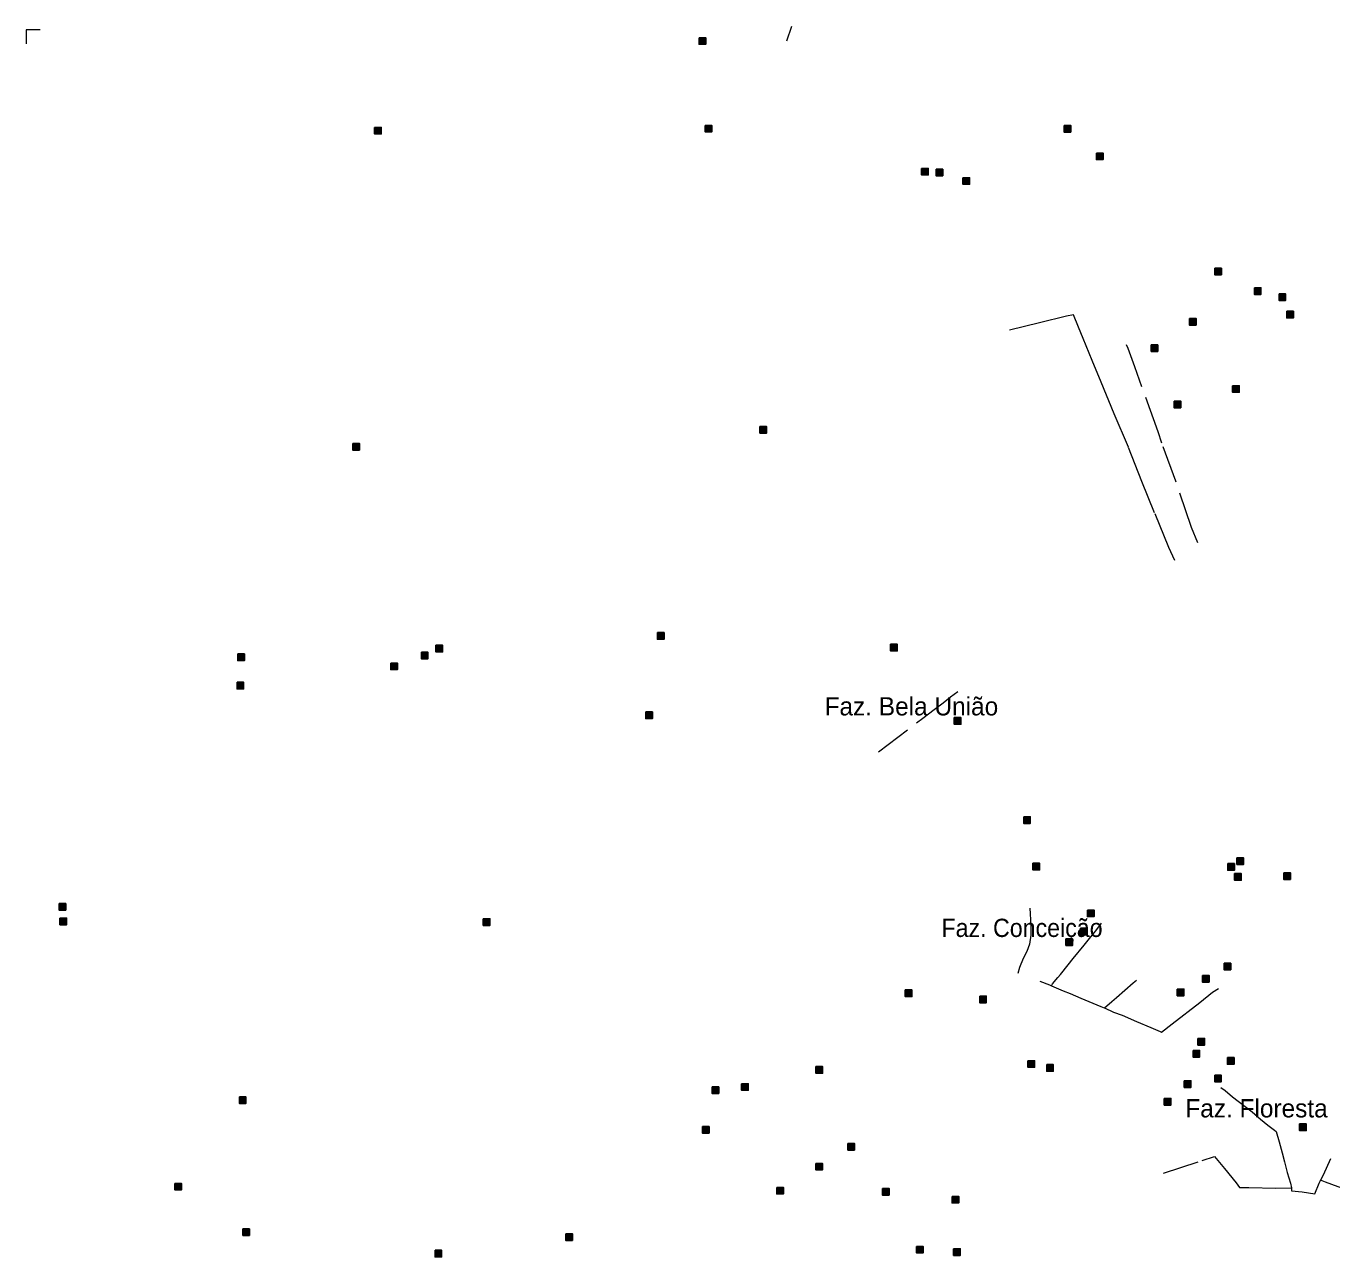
# Model space of a CAD drawing. Extents: x 393.5 to 446.9, y 8064.8 to 8120.4.
# Drawn here: x 393.54 to 404.99, y 8109.39 to 8120.19 of the extents above; entities that cross this region are included whole.
import ezdxf

# ---------------------------------------------------------------- set-up
doc = ezdxf.new("R2010")
doc.units = 0
doc.header["$LTSCALE"] = 0.064
doc.linetypes.add('DOT_DASHED', pattern=[7.7, 5, -1.2, 0.3, -1.2])
for name, color, linetype, lineweight in [('2', 7, 'Continuous', 25), ('22', 7, 'DOT_DASHED', 13), ('63', 7, 'Continuous', 13)]:
    doc.layers.add(name, color=color, linetype=linetype, lineweight=lineweight)
doc.layers.add('61', color=7, linetype='Continuous')

msp = doc.modelspace()

# ---------------------------------------------------------------- hatches: boundary and pattern name
at = {"layer": '2'}
for points in [[(399.4403, 8120.0847), (399.4983, 8120.0847), (399.4983, 8120.0267), (399.4403, 8120.0267)], [(399.4938, 8119.3158), (399.5518, 8119.3158), (399.5518, 8119.2578), (399.4938, 8119.2578)], [(402.6411, 8119.3152), (402.6991, 8119.3152), (402.6991, 8119.2572), (402.6411, 8119.2572)], [(396.5954, 8119.2985), (396.6534, 8119.2985), (396.6534, 8119.2405), (396.5954, 8119.2405)], [(402.9245, 8119.0735), (402.9825, 8119.0735), (402.9825, 8119.0155), (402.9245, 8119.0155)], [(401.3912, 8118.939), (401.4492, 8118.939), (401.4492, 8118.881), (401.3912, 8118.881)], [(401.5188, 8118.9317), (401.5768, 8118.9317), (401.5768, 8118.8737), (401.5188, 8118.8737)], [(401.7537, 8118.8571), (401.8117, 8118.8571), (401.8117, 8118.7991), (401.7537, 8118.7991)], [(403.962, 8118.0636), (404.02, 8118.0636), (404.02, 8118.0056), (403.962, 8118.0056)], [(404.3084, 8117.8916), (404.3664, 8117.8916), (404.3664, 8117.8336), (404.3084, 8117.8336)], [(404.525, 8117.8386), (404.583, 8117.8386), (404.583, 8117.7806), (404.525, 8117.7806)], [(403.7391, 8117.6229), (403.7971, 8117.6229), (403.7971, 8117.5649), (403.7391, 8117.5649)], [(404.5926, 8117.6855), (404.6506, 8117.6855), (404.6506, 8117.6275), (404.5926, 8117.6275)], [(403.4041, 8117.3912), (403.4621, 8117.3912), (403.4621, 8117.3332), (403.4041, 8117.3332)], [(404.1183, 8117.0334), (404.1763, 8117.0334), (404.1763, 8116.9754), (404.1183, 8116.9754)], [(403.6054, 8116.8983), (403.6634, 8116.8983), (403.6634, 8116.8403), (403.6054, 8116.8403)], [(399.974, 8116.6752), (400.032, 8116.6752), (400.032, 8116.6172), (399.974, 8116.6172)], [(396.4044, 8116.5271), (396.4624, 8116.5271), (396.4624, 8116.4691), (396.4044, 8116.4691)], [(399.075, 8114.868), (399.133, 8114.868), (399.133, 8114.81), (399.075, 8114.81)], [(397.133, 8114.7574), (397.191, 8114.7574), (397.191, 8114.6994), (397.133, 8114.6994)], [(401.1191, 8114.7664), (401.1771, 8114.7664), (401.1771, 8114.7084), (401.1191, 8114.7084)], [(395.3962, 8114.6811), (395.4542, 8114.6811), (395.4542, 8114.6231), (395.3962, 8114.6231)], [(397.0057, 8114.6965), (397.0637, 8114.6965), (397.0637, 8114.6385), (397.0057, 8114.6385)], [(396.7378, 8114.6018), (396.7958, 8114.6018), (396.7958, 8114.5438), (396.7378, 8114.5438)], [(395.3893, 8114.4324), (395.4473, 8114.4324), (395.4473, 8114.3744), (395.3893, 8114.3744)], [(398.9733, 8114.1723), (399.0313, 8114.1723), (399.0313, 8114.1143), (398.9733, 8114.1143)], [(401.6779, 8114.1229), (401.7359, 8114.1229), (401.7359, 8114.0649), (401.6779, 8114.0649)], [(402.2864, 8113.2538), (402.3444, 8113.2538), (402.3444, 8113.1958), (402.2864, 8113.1958)], [(402.3674, 8112.8458), (402.4254, 8112.8458), (402.4254, 8112.7878), (402.3674, 8112.7878)], [(404.0754, 8112.8425), (404.1334, 8112.8425), (404.1334, 8112.7845), (404.0754, 8112.7845)], [(404.1564, 8112.8933), (404.2144, 8112.8933), (404.2144, 8112.8353), (404.1564, 8112.8353)], [(404.1359, 8112.7551), (404.1939, 8112.7551), (404.1939, 8112.6971), (404.1359, 8112.6971)], [(404.5662, 8112.7621), (404.6242, 8112.7621), (404.6242, 8112.7041), (404.5662, 8112.7041)], [(393.8298, 8112.493), (393.8878, 8112.493), (393.8878, 8112.435), (393.8298, 8112.435)], [(393.8365, 8112.365), (393.8945, 8112.365), (393.8945, 8112.307), (393.8365, 8112.307)], [(397.548, 8112.3591), (397.606, 8112.3591), (397.606, 8112.3011), (397.548, 8112.3011)], [(402.8452, 8112.4361), (402.9032, 8112.4361), (402.9032, 8112.3781), (402.8452, 8112.3781)], [(402.7843, 8112.2773), (402.8423, 8112.2773), (402.8423, 8112.2193), (402.7843, 8112.2193)], [(402.6566, 8112.1831), (402.7146, 8112.1831), (402.7146, 8112.1251), (402.6566, 8112.1251)], [(404.0439, 8111.9698), (404.1019, 8111.9698), (404.1019, 8111.9118), (404.0439, 8111.9118)], [(403.8534, 8111.8626), (403.9114, 8111.8626), (403.9114, 8111.8046), (403.8534, 8111.8046)], [(401.2482, 8111.7356), (401.3062, 8111.7356), (401.3062, 8111.6776), (401.2482, 8111.6776)], [(401.9004, 8111.6812), (401.9584, 8111.6812), (401.9584, 8111.6232), (401.9004, 8111.6232)], [(403.6333, 8111.7423), (403.6913, 8111.7423), (403.6913, 8111.6843), (403.6333, 8111.6843)], [(403.8138, 8111.3103), (403.8718, 8111.3103), (403.8718, 8111.2523), (403.8138, 8111.2523)], [(403.7707, 8111.205), (403.8287, 8111.205), (403.8287, 8111.147), (403.7707, 8111.147)], [(402.3236, 8111.1151), (402.3816, 8111.1151), (402.3816, 8111.0571), (402.3236, 8111.0571)], [(402.4878, 8111.0805), (402.5458, 8111.0805), (402.5458, 8111.0225), (402.4878, 8111.0225)], [(404.0729, 8111.1421), (404.1309, 8111.1421), (404.1309, 8111.0841), (404.0729, 8111.0841)], [(400.4649, 8111.0626), (400.5229, 8111.0626), (400.5229, 8111.0046), (400.4649, 8111.0046)], [(403.9608, 8110.9877), (404.0188, 8110.9877), (404.0188, 8110.9297), (403.9608, 8110.9297)], [(399.5543, 8110.8855), (399.6123, 8110.8855), (399.6123, 8110.8275), (399.5543, 8110.8275)], [(399.813, 8110.9134), (399.871, 8110.9134), (399.871, 8110.8554), (399.813, 8110.8554)], [(403.6938, 8110.9385), (403.7518, 8110.9385), (403.7518, 8110.8805), (403.6938, 8110.8805)], [(395.4101, 8110.7976), (395.4681, 8110.7976), (395.4681, 8110.7396), (395.4101, 8110.7396)], [(403.5184, 8110.784), (403.5764, 8110.784), (403.5764, 8110.726), (403.5184, 8110.726)], [(399.4703, 8110.5378), (399.5283, 8110.5378), (399.5283, 8110.4798), (399.4703, 8110.4798)], [(404.7057, 8110.5603), (404.7637, 8110.5603), (404.7637, 8110.5023), (404.7057, 8110.5023)], [(400.7448, 8110.3893), (400.8028, 8110.3893), (400.8028, 8110.3313), (400.7448, 8110.3313)], [(400.464, 8110.2147), (400.522, 8110.2147), (400.522, 8110.1567), (400.464, 8110.1567)], [(394.8446, 8110.0392), (394.9026, 8110.0392), (394.9026, 8109.9812), (394.8446, 8109.9812)], [(400.1214, 8110.0042), (400.1794, 8110.0042), (400.1794, 8109.9462), (400.1214, 8109.9462)], [(401.0482, 8109.9946), (401.1062, 8109.9946), (401.1062, 8109.9366), (401.0482, 8109.9366)], [(401.6586, 8109.9253), (401.7166, 8109.9253), (401.7166, 8109.8673), (401.6586, 8109.8673)], [(395.4406, 8109.6405), (395.4986, 8109.6405), (395.4986, 8109.5825), (395.4406, 8109.5825)], [(398.2716, 8109.5972), (398.3296, 8109.5972), (398.3296, 8109.5392), (398.2716, 8109.5392)], [(401.3467, 8109.4868), (401.4047, 8109.4868), (401.4047, 8109.4288), (401.3467, 8109.4288)], [(401.672, 8109.4663), (401.73, 8109.4663), (401.73, 8109.4083), (401.672, 8109.4083)], [(397.1255, 8109.4527), (397.1835, 8109.4527), (397.1835, 8109.3947), (397.1255, 8109.3947)]]:
    msp.add_hatch(color=256, dxfattribs=at).paths.add_polyline_path(points)

# ---------------------------------------------------------------- linework, layer by layer
for points in [[(399.4403, 8120.0847), (399.4983, 8120.0847), (399.4983, 8120.0267), (399.4403, 8120.0267)], [(399.4938, 8119.3158), (399.5518, 8119.3158), (399.5518, 8119.2578), (399.4938, 8119.2578)], [(402.6411, 8119.3152), (402.6991, 8119.3152), (402.6991, 8119.2572), (402.6411, 8119.2572)], [(396.5954, 8119.2985), (396.6534, 8119.2985), (396.6534, 8119.2405), (396.5954, 8119.2405)], [(402.9245, 8119.0735), (402.9825, 8119.0735), (402.9825, 8119.0155), (402.9245, 8119.0155)], [(401.3912, 8118.939), (401.4492, 8118.939), (401.4492, 8118.881), (401.3912, 8118.881)], [(401.5188, 8118.9317), (401.5768, 8118.9317), (401.5768, 8118.8737), (401.5188, 8118.8737)], [(401.7537, 8118.8571), (401.8117, 8118.8571), (401.8117, 8118.7991), (401.7537, 8118.7991)], [(403.962, 8118.0636), (404.02, 8118.0636), (404.02, 8118.0056), (403.962, 8118.0056)], [(404.3084, 8117.8916), (404.3664, 8117.8916), (404.3664, 8117.8336), (404.3084, 8117.8336)], [(404.525, 8117.8386), (404.583, 8117.8386), (404.583, 8117.7806), (404.525, 8117.7806)], [(403.7391, 8117.6229), (403.7971, 8117.6229), (403.7971, 8117.5649), (403.7391, 8117.5649)], [(404.5926, 8117.6855), (404.6506, 8117.6855), (404.6506, 8117.6275), (404.5926, 8117.6275)], [(403.4041, 8117.3912), (403.4621, 8117.3912), (403.4621, 8117.3332), (403.4041, 8117.3332)], [(404.1183, 8117.0334), (404.1763, 8117.0334), (404.1763, 8116.9754), (404.1183, 8116.9754)], [(403.6054, 8116.8983), (403.6634, 8116.8983), (403.6634, 8116.8403), (403.6054, 8116.8403)], [(399.974, 8116.6752), (400.032, 8116.6752), (400.032, 8116.6172), (399.974, 8116.6172)], [(396.4044, 8116.5271), (396.4624, 8116.5271), (396.4624, 8116.4691), (396.4044, 8116.4691)], [(399.075, 8114.868), (399.133, 8114.868), (399.133, 8114.81), (399.075, 8114.81)], [(397.133, 8114.7574), (397.191, 8114.7574), (397.191, 8114.6994), (397.133, 8114.6994)], [(401.1191, 8114.7664), (401.1771, 8114.7664), (401.1771, 8114.7084), (401.1191, 8114.7084)], [(395.3962, 8114.6811), (395.4542, 8114.6811), (395.4542, 8114.6231), (395.3962, 8114.6231)], [(397.0057, 8114.6965), (397.0637, 8114.6965), (397.0637, 8114.6385), (397.0057, 8114.6385)], [(396.7378, 8114.6018), (396.7958, 8114.6018), (396.7958, 8114.5438), (396.7378, 8114.5438)], [(395.3893, 8114.4324), (395.4473, 8114.4324), (395.4473, 8114.3744), (395.3893, 8114.3744)], [(398.9733, 8114.1723), (399.0313, 8114.1723), (399.0313, 8114.1143), (398.9733, 8114.1143)], [(401.6779, 8114.1229), (401.7359, 8114.1229), (401.7359, 8114.0649), (401.6779, 8114.0649)], [(402.2864, 8113.2538), (402.3444, 8113.2538), (402.3444, 8113.1958), (402.2864, 8113.1958)], [(402.3674, 8112.8458), (402.4254, 8112.8458), (402.4254, 8112.7878), (402.3674, 8112.7878)], [(404.0754, 8112.8425), (404.1334, 8112.8425), (404.1334, 8112.7845), (404.0754, 8112.7845)], [(404.1564, 8112.8933), (404.2144, 8112.8933), (404.2144, 8112.8353), (404.1564, 8112.8353)], [(404.1359, 8112.7551), (404.1939, 8112.7551), (404.1939, 8112.6971), (404.1359, 8112.6971)], [(404.5662, 8112.7621), (404.6242, 8112.7621), (404.6242, 8112.7041), (404.5662, 8112.7041)], [(393.8298, 8112.493), (393.8878, 8112.493), (393.8878, 8112.435), (393.8298, 8112.435)], [(393.8365, 8112.365), (393.8945, 8112.365), (393.8945, 8112.307), (393.8365, 8112.307)], [(397.548, 8112.3591), (397.606, 8112.3591), (397.606, 8112.3011), (397.548, 8112.3011)], [(402.8452, 8112.4361), (402.9032, 8112.4361), (402.9032, 8112.3781), (402.8452, 8112.3781)], [(402.7843, 8112.2773), (402.8423, 8112.2773), (402.8423, 8112.2193), (402.7843, 8112.2193)], [(402.6566, 8112.1831), (402.7146, 8112.1831), (402.7146, 8112.1251), (402.6566, 8112.1251)], [(404.0439, 8111.9698), (404.1019, 8111.9698), (404.1019, 8111.9118), (404.0439, 8111.9118)], [(403.8534, 8111.8626), (403.9114, 8111.8626), (403.9114, 8111.8046), (403.8534, 8111.8046)], [(401.2482, 8111.7356), (401.3062, 8111.7356), (401.3062, 8111.6776), (401.2482, 8111.6776)], [(401.9004, 8111.6812), (401.9584, 8111.6812), (401.9584, 8111.6232), (401.9004, 8111.6232)], [(403.6333, 8111.7423), (403.6913, 8111.7423), (403.6913, 8111.6843), (403.6333, 8111.6843)], [(403.8138, 8111.3103), (403.8718, 8111.3103), (403.8718, 8111.2523), (403.8138, 8111.2523)], [(403.7707, 8111.205), (403.8287, 8111.205), (403.8287, 8111.147), (403.7707, 8111.147)], [(402.3236, 8111.1151), (402.3816, 8111.1151), (402.3816, 8111.0571), (402.3236, 8111.0571)], [(402.4878, 8111.0805), (402.5458, 8111.0805), (402.5458, 8111.0225), (402.4878, 8111.0225)], [(404.0729, 8111.1421), (404.1309, 8111.1421), (404.1309, 8111.0841), (404.0729, 8111.0841)], [(400.4649, 8111.0626), (400.5229, 8111.0626), (400.5229, 8111.0046), (400.4649, 8111.0046)], [(403.9608, 8110.9877), (404.0188, 8110.9877), (404.0188, 8110.9297), (403.9608, 8110.9297)], [(399.5543, 8110.8855), (399.6123, 8110.8855), (399.6123, 8110.8275), (399.5543, 8110.8275)], [(399.813, 8110.9134), (399.871, 8110.9134), (399.871, 8110.8554), (399.813, 8110.8554)], [(403.6938, 8110.9385), (403.7518, 8110.9385), (403.7518, 8110.8805), (403.6938, 8110.8805)], [(395.4101, 8110.7976), (395.4681, 8110.7976), (395.4681, 8110.7396), (395.4101, 8110.7396)], [(403.5184, 8110.784), (403.5764, 8110.784), (403.5764, 8110.726), (403.5184, 8110.726)], [(399.4703, 8110.5378), (399.5283, 8110.5378), (399.5283, 8110.4798), (399.4703, 8110.4798)], [(404.7057, 8110.5603), (404.7637, 8110.5603), (404.7637, 8110.5023), (404.7057, 8110.5023)], [(400.7448, 8110.3893), (400.8028, 8110.3893), (400.8028, 8110.3313), (400.7448, 8110.3313)], [(400.464, 8110.2147), (400.522, 8110.2147), (400.522, 8110.1567), (400.464, 8110.1567)], [(394.8446, 8110.0392), (394.9026, 8110.0392), (394.9026, 8109.9812), (394.8446, 8109.9812)], [(400.1214, 8110.0042), (400.1794, 8110.0042), (400.1794, 8109.9462), (400.1214, 8109.9462)], [(401.0482, 8109.9946), (401.1062, 8109.9946), (401.1062, 8109.9366), (401.0482, 8109.9366)], [(401.6586, 8109.9253), (401.7166, 8109.9253), (401.7166, 8109.8673), (401.6586, 8109.8673)], [(395.4406, 8109.6405), (395.4986, 8109.6405), (395.4986, 8109.5825), (395.4406, 8109.5825)], [(398.2716, 8109.5972), (398.3296, 8109.5972), (398.3296, 8109.5392), (398.2716, 8109.5392)], [(401.3467, 8109.4868), (401.4047, 8109.4868), (401.4047, 8109.4288), (401.3467, 8109.4288)], [(401.672, 8109.4663), (401.73, 8109.4663), (401.73, 8109.4083), (401.672, 8109.4083)], [(397.1255, 8109.4527), (397.1835, 8109.4527), (397.1835, 8109.3947), (397.1255, 8109.3947)]]:
    msp.add_lwpolyline(points, close=True, dxfattribs=at)
at = {"layer": '22'}
msp.add_line((400.2104, 8120.058), (400.255, 8120.1861), dxfattribs=at)
for points in [[(402.7664, 8117.546), (402.7226, 8117.6555), (402.6622, 8117.6416), (402.4253, 8117.5859), (402.1605, 8117.5209)], [(403.6108, 8115.4997), (403.5589, 8115.6135), (403.4334, 8115.9198), (403.3219, 8116.1936), (403.2046, 8116.493), (403.0781, 8116.7854), (402.9667, 8117.0648), (402.8877, 8117.2528), (402.8088, 8117.4478), (402.7664, 8117.546)], [(403.8123, 8115.6552), (403.7563, 8115.7885), (403.6193, 8116.1969), (403.4973, 8116.5288), (403.4648, 8116.6286), (403.3233, 8117.0232), (403.2616, 8117.2001), (403.2024, 8117.3591), (403.1881, 8117.3917)], [(401.0125, 8113.8228), (401.4008, 8114.1177), (401.5018, 8114.1934), (401.5791, 8114.2533), (401.6438, 8114.3038), (401.6754, 8114.3274), (401.7085, 8114.3511)], [(402.3406, 8112.453), (402.3491, 8112.3009), (402.3491, 8112.2147), (402.3386, 8112.137), (402.3133, 8112.0717), (402.2817, 8112.0108), (402.2501, 8111.9309), (402.2351, 8111.8786)], [(402.6194, 8111.8859), (402.7214, 8112.0095), (402.8174, 8112.1285), (402.8753, 8112.1996), (402.9183, 8112.2541), (402.9679, 8112.3202)], [(402.5313, 8111.7721), (402.54, 8111.7886), (402.5871, 8111.8431), (402.6078, 8111.8704), (402.6194, 8111.8859)], [(402.4291, 8111.8117), (402.5118, 8111.7786), (402.5313, 8111.7721)], [(402.5313, 8111.7721), (402.5722, 8111.753), (402.6318, 8111.7266), (402.693, 8111.7034), (402.7873, 8111.6621), (402.9631, 8111.5887), (402.9927, 8111.5781), (402.9954, 8111.5771)], [(402.9954, 8111.5771), (403.0588, 8111.6344), (403.0992, 8111.6683), (403.1745, 8111.7326), (403.2471, 8111.7987), (403.2756, 8111.8216)], [(402.9954, 8111.5771), (403.0728, 8111.5408), (403.1489, 8111.5143), (403.2758, 8111.459), (403.4018, 8111.4061), (403.4819, 8111.37), (403.4946, 8111.3637), (403.5874, 8111.4372), (403.8309, 8111.626), (403.9413, 8111.7156), (403.9943, 8111.7479)], [(404.0142, 8110.879), (404.053, 8110.853), (404.1172, 8110.7973), (404.2894, 8110.6658), (404.3628, 8110.6033), (404.427, 8110.551), (404.4843, 8110.5071), (404.5012, 8110.4936), (404.5274, 8110.4043), (404.551, 8110.3081), (404.5737, 8110.2271), (404.5974, 8110.136), (404.6261, 8110.0415), (404.6347, 8109.9996)], [(403.5117, 8110.1301), (403.8522, 8110.2408), (403.9586, 8110.2762), (404.0463, 8110.17), (404.1493, 8110.0435), (404.1797, 8110.003), (404.2607, 8110.003), (404.4979, 8109.9962), (404.6294, 8109.9995), (404.6328, 8109.9996), (404.633, 8109.9996), (404.6347, 8109.9996)], [(404.9757, 8110.2543), (404.9115, 8110.1109), (404.8896, 8110.067)], [(404.6347, 8109.9996), (404.633, 8109.9743), (404.7275, 8109.9641), (404.8389, 8109.949), (404.8778, 8110.04), (404.8881, 8110.0636), (404.8896, 8110.067)], [(406.0607, 8109.6581), (406.0233, 8109.6712), (405.9651, 8109.6881), (405.8537, 8109.7252), (405.7389, 8109.769), (405.6427, 8109.8011), (405.5735, 8109.8247), (405.457, 8109.8652), (405.2983, 8109.9175), (405.224, 8109.9411), (405.1312, 8109.9782), (404.9318, 8110.0502), (404.8896, 8110.067)]]:
    msp.add_lwpolyline(points, dxfattribs=at)
at = {"layer": '63'}
msp.add_lwpolyline([(393.6636, 8120.153), (393.5404, 8120.153), (393.5404, 8120.0316)], dxfattribs=at)

# ---------------------------------------------------------------- texts
at = {"layer": '61'}
for s, p in [('Faz. Bela União', (400.5407, 8114.1423)), ('Faz. Floresta', (403.7032, 8110.6176))]:
    msp.add_text(s, height=0.16, dxfattribs=at).set_placement(p)
at = {"layer": '61', "width": 0.95}
msp.add_text('Faz. Conceição', height=0.16, dxfattribs=at).set_placement((401.5657, 8112.1997))

doc.saveas('drawing.dxf')
